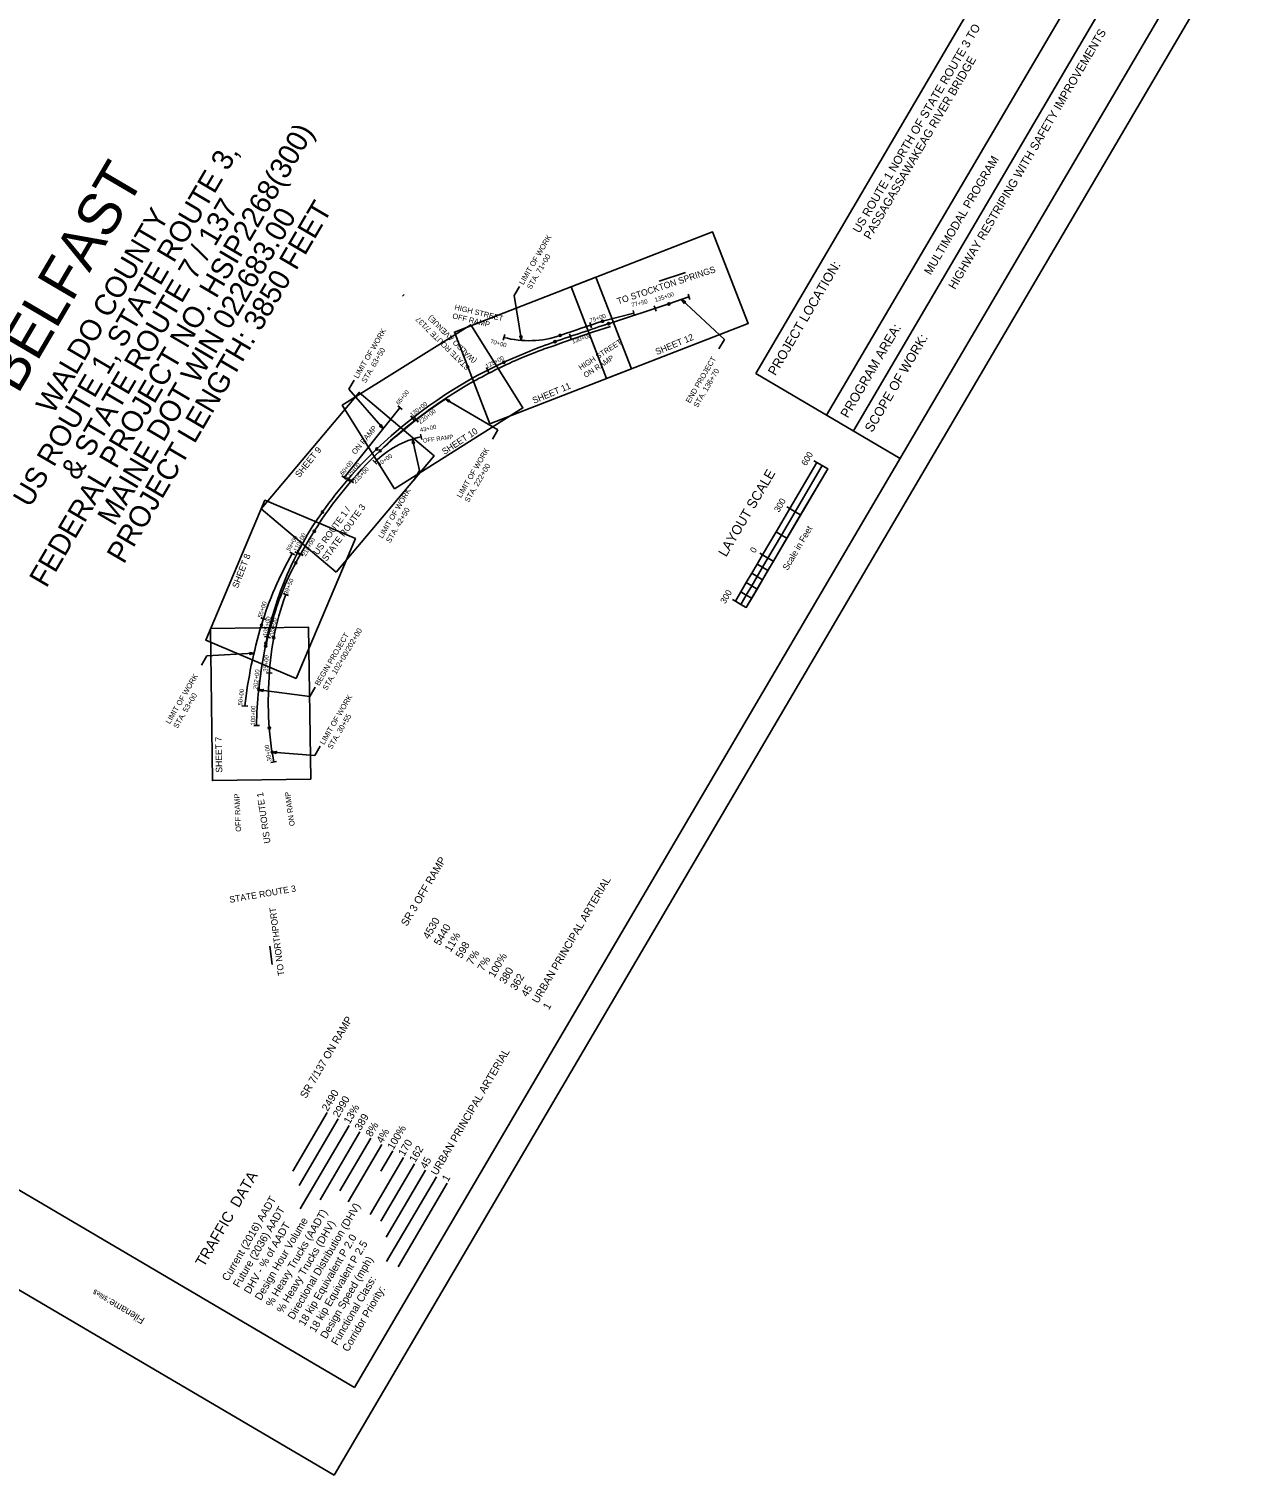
# Model space of a CAD drawing. Extents: x 423683 to 425040, y 89137 to 90655.
# Drawn here: x 424180 to 425040, y 89137 to 90149 of the extents above; entities that cross this region are included whole.
import ezdxf

# ---------------------------------------------------------------- set-up
doc = ezdxf.new("R2010")
doc.units = 0
for name, color, linetype in [('ANNOTATION', 7, 'Continuous'), ('BORDER', 7, 'Continuous'), ('D_Roadway_Centerline_Text', 7, 'Continuous'), ('D_Roadway_Edge_TW', 7, 'Continuous'), ('PLOT BOUNDARY', 7, 'Continuous'), ('Rte 1 Construction Alignment', 7, 'Continuous'), ('S_Curb_Type_5', 7, 'Continuous'), ('SHADING', 7, 'Continuous')]:
    doc.layers.add(name, color=color, linetype=linetype)

msp = doc.modelspace()

# ---------------------------------------------------------------- linework, layer by layer
at = {"layer": 'ANNOTATION'}
for p, q in [((424523.6, 89968.7), (424519.8, 89962.3)), ((424621.2, 89972.3), (424639.6, 89978.4)), ((424525, 89930.9), (424519.8, 89962.3)), ((424637, 89959.4), (424666.9, 89931.6)), ((424663.1, 89925.1), (424666.9, 89931.6)), ((424408, 89903.2), (424404.2, 89896.7)), ((424428.2, 89869.2), (424404.2, 89896.7)), ((424471.8, 89889.9), (424508.5, 89868.3)), ((424504.7, 89861.8), (424508.5, 89868.3)), ((424448.7, 89861.8), (424453.6, 89840)), ((424449.8, 89833.5), (424453.6, 89840)), ((424301, 89703.8), (424304.8, 89710.2)), ((424337.8, 89712.1), (424304.8, 89710.2)), ((424341.2, 89686.5), (424376.9, 89681.8)), ((424380.7, 89688.3), (424376.9, 89681.8)), ((424384.2, 89647.2), (424380.4, 89640.7)), ((424350.5, 89642.9), (424380.4, 89640.7)), ((424349, 89507.2), (424350.6, 89494.3)), ((424364.9, 89349.8), (424389, 89390.9)), ((424369.4, 89339.9), (424396.7, 89386.4)), ((424370.1, 89323.6), (424404.3, 89381.9)), ((424384.1, 89329.9), (424411.9, 89377.4)), ((424397.9, 89336), (424419.6, 89372.9)), ((424403.7, 89328.4), (424427.2, 89368.5)), ((424426.6, 89349.9), (424434.9, 89364)), ((424419, 89319.5), (424442.5, 89359.5)), ((424426.6, 89315), (424450.1, 89355)), ((424430.3, 89303.8), (424457.8, 89350.5)), ((424430.5, 89286.6), (424465.4, 89346)), ((424438.7, 89283), (424473, 89341.5))]:
    msp.add_line(p, q, dxfattribs=at)
for points in [[(424584.5, 89904.3), (424683.6, 89942.7), (424658.7, 90006.8), (424559.6, 89968.4)], [(424502.8, 89872.6), (424601.9, 89911), (424577, 89975.1), (424478, 89936.7)], [(424638.7, 89956.8), (424637, 89959.4), (424639.7, 89957.9)], [(424436, 89827.2), (424526, 89883.7), (424489.5, 89941.9), (424399.5, 89885.5)], [(424525.2, 89934), (424525, 89930.9), (424523.7, 89933.8)], [(424395.4, 89768.9), (424463.9, 89850.1), (424411.3, 89894.5), (424342.8, 89813.2)], [(424474, 89887.7), (424471.8, 89889.9), (424474.7, 89889)], [(424426.8, 89872), (424428.2, 89869.2), (424425.7, 89871)], [(424448.6, 89858.7), (424448.7, 89861.8), (424450.1, 89859.1)], [(424367.4, 89694.4), (424408.8, 89792.3), (424345.5, 89819.1), (424304.1, 89721.2)], [(424377.5, 89624.1), (424376, 89730.3), (424307.3, 89729.4), (424308.7, 89623.1)], [(424334.8, 89712.7), (424337.8, 89712.1), (424334.9, 89711.2)], [(424344.1, 89685.4), (424341.2, 89686.5), (424344.3, 89686.8)], [(424353.4, 89641.9), (424350.5, 89642.9), (424353.6, 89643.4)]]:
    msp.add_lwpolyline(points, close=True, dxfattribs=at)
at = {"layer": 'BORDER'}
for p, q in [((424408.2, 89198.5), (425015.8, 90233.3)), ((424876.8, 90228), (424688.8, 89907.7)), ((424738.4, 89878.6), (424926.5, 90198.8)), ((424757.2, 89867.6), (424945.2, 90187.8)), ((424688.8, 89907.7), (424789.8, 89848.4)), ((424731.6, 89845.6), (424729.6, 89846.7)), ((424712.6, 89813.3), (424710.6, 89814.4)), ((424691.7, 89782.1), (424693.6, 89780.9)), ((424674.6, 89748.6), (424672.7, 89749.7)), ((423729.1, 89597.3), (424408.2, 89198.5))]:
    msp.add_line(p, q, dxfattribs=at)
for points in [[(424682.2, 89744.1), (424739.2, 89841.1), (424731.6, 89845.6)], [(424712.6, 89813.3), (424731.6, 89845.6), (424735.4, 89843.3), (424716.4, 89811), (424712.6, 89813.3)], [(424716.4, 89811), (424735.4, 89843.3), (424739.2, 89841.1), (424720.2, 89808.8), (424716.4, 89811)], [(424716.4, 89811), (424706.9, 89794.8), (424703.1, 89797.1), (424712.6, 89813.3), (424716.4, 89811)], [(424720.2, 89808.8), (424710.7, 89792.6), (424706.9, 89794.8), (424716.4, 89811), (424720.2, 89808.8)], [(424706.9, 89794.8), (424697.4, 89778.7), (424693.6, 89780.9), (424703.1, 89797.1), (424706.9, 89794.8)], [(424710.7, 89792.6), (424701.2, 89776.4), (424697.4, 89778.7), (424706.9, 89794.8), (424710.7, 89792.6)], [(424689.8, 89774.4), (424693.6, 89780.9), (424697.4, 89778.7), (424693.6, 89772.2), (424689.8, 89774.4)], [(424693.6, 89772.2), (424697.4, 89778.7), (424701.2, 89776.4), (424697.4, 89770), (424693.6, 89772.2)], [(424682.2, 89761.5), (424686, 89768), (424689.8, 89765.7), (424686, 89759.3), (424682.2, 89761.5)], [(424686, 89768), (424689.8, 89774.4), (424693.6, 89772.2), (424689.8, 89765.7), (424686, 89768)], [(424689.8, 89765.7), (424693.6, 89772.2), (424697.4, 89770), (424693.6, 89763.5), (424689.8, 89765.7)], [(424678.4, 89755), (424682.2, 89761.5), (424686, 89759.3), (424682.2, 89752.8), (424678.4, 89755)], [(424682.2, 89752.8), (424686, 89759.3), (424689.8, 89757), (424686, 89750.6), (424682.2, 89752.8)], [(424686, 89759.3), (424689.8, 89765.7), (424693.6, 89763.5), (424689.8, 89757), (424686, 89759.3)], [(424674.6, 89748.6), (424678.4, 89755), (424682.2, 89752.8), (424678.4, 89746.3), (424674.6, 89748.6)], [(424678.4, 89746.3), (424682.2, 89752.8), (424686, 89750.6), (424682.2, 89744.1), (424678.4, 89746.3)]]:
    msp.add_lwpolyline(points, dxfattribs=at)
for points in [[(424716.4, 89811), (424735.4, 89843.3), (424739.2, 89841.1), (424720.2, 89808.8)], [(424706.9, 89794.8), (424716.4, 89811), (424712.6, 89813.3), (424703.1, 89797.1)], [(424697.4, 89778.7), (424706.9, 89794.8), (424710.7, 89792.6), (424701.2, 89776.4)], [(424693.6, 89772.2), (424697.4, 89778.7), (424693.6, 89780.9), (424689.8, 89774.4)], [(424686, 89759.3), (424689.8, 89765.7), (424686, 89768), (424682.2, 89761.5)], [(424689.8, 89765.7), (424693.6, 89772.2), (424697.4, 89770), (424693.6, 89763.5)], [(424682.2, 89752.8), (424686, 89759.3), (424689.8, 89757), (424686, 89750.6)], [(424674.6, 89748.6), (424678.4, 89755), (424682.2, 89752.8), (424678.4, 89746.3)]]:
    msp.add_lwpolyline(points, close=True, dxfattribs=at)
at = {"layer": 'D_Roadway_Centerline_Text'}
for points in [[(424641.5, 89963.2), (424642.8, 89959.4)], [(424603, 89951.9), (424604, 89948)], [(424603.4, 89950.2), (424603.5, 89949.7)], [(424617.8, 89955.2), (424619.1, 89951.4)], [(424572.7, 89943.5), (424574, 89939.7)], [(424513.2, 89935), (424512.1, 89931.1)], [(424558.5, 89935.5), (424559.8, 89931.7)], [(424500.4, 89911.9), (424502.2, 89908.3)], [(424471.6, 89890.1), (424471.9, 89889.6)], [(424438.4, 89885.1), (424441.5, 89882.6)], [(424447.5, 89878.1), (424449.9, 89875)], [(424450.2, 89876.9), (424452.6, 89873.8)], [(424454.3, 89865.4), (424455.2, 89861.5)], [(424420.9, 89847.1), (424423.7, 89844.3)], [(424399.3, 89836.3), (424402.4, 89833.8)], [(424401.9, 89834.8), (424405, 89832.2)], [(424404.5, 89833.9), (424407.5, 89831.3)], [(424362.9, 89782.9), (424366.4, 89780.9)], [(424366.4, 89783.1), (424369.9, 89781.2)], [(424368.6, 89782.3), (424372.1, 89780.4)], [(424358.3, 89753.9), (424362, 89752.4)], [(424342.6, 89736.8), (424346.4, 89735.6)], [(424345.1, 89723.9), (424349, 89723.1)], [(424345.6, 89723.9), (424349.4, 89722.9)], [(424346.6, 89698.5), (424350.6, 89698.2)], [(424329.4, 89675.4), (424333.4, 89675)], [(424337.6, 89661.6), (424341.6, 89661.5)], [(424349.7, 89635.8), (424353.6, 89636.5)]]:
    msp.add_lwpolyline(points, dxfattribs=at)
at = {"layer": 'D_Roadway_Edge_TW'}
for p, q in [((424628.1, 89956.4), (424642.1, 89961.3)), ((424581.6, 89944.3), (424603.5, 89949.9)), ((424585.9, 89942.6), (424628.1, 89956.4)), ((424400.8, 89835.1), (424439.9, 89883.8)), ((424351.7, 89636.1), (424350.5, 89642.9))]:
    msp.add_line(p, q, dxfattribs=at)
for centre, radius, start, end in [((425487.9, 87197.2), 2889.8, 108.1874, 108.9737), ((425487.9, 87197.2), 2892.8, 108.2581, 108.877), ((424530.2, 89998.2), 67.5, 254.9678, 288.877), ((424670.8, 89573.8), 376.6, 108.9737, 114.8373), ((424649.8, 89619.2), 326.6, 114.8373, 133.776), ((424651, 89617), 326.5, 123.3035, 133.5362), ((424468.4, 89799.9), 65, 102.0988, 135.1541), ((424629.9, 89639.2), 295.9, 133.5362, 147.6604), ((424639, 89630.5), 311, 133.776, 144.5408), ((424579.1, 89673.1), 237.5, 144.5408, 168.8381), ((424671.7, 89612.8), 345.3, 147.6604, 151.9147), ((424574.6, 89661.9), 241.9, 150.2569, 163.2266), ((424548.7, 89678.4), 205.9, 151.9112, 164.4564), ((424501.1, 89697.3), 151.6, 158.3641, 170.2343), ((424654.2, 89637.9), 325, 163.2266, 173.4073), ((424547.3, 89672.9), 206.1, 162.8833, 167.5733), ((424708.9, 89647.5), 369.8, 168.8381, 173.9451), ((424644.7, 89654.3), 305.3, 168.0988, 173.9451), ((424610.3, 89678.5), 262.5, 170.2343, 184.0825), ((424644.7, 89654.3), 305.3, 173.9451, 178.6375), ((424524.9, 89672.4), 176.9, 184.0825, 189.5944)]:
    msp.add_arc(centre, radius, start, end, dxfattribs=at)
at = {"layer": 'PLOT BOUNDARY'}
msp.add_lwpolyline([(424394, 89137.3), (425039.6, 90236.7), (424328.2, 90654.5), (423682.6, 89555.1)], close=True, dxfattribs=at)
at = {"layer": 'Rte 1 Construction Alignment'}
for centre in [(424628.1, 89956.4), (424581.6, 89944.3), (424585.9, 89942.6), (424548.4, 89930), (424552, 89934.4), (424512.6, 89915.6), (424423.8, 89855), (424426.1, 89853.7), (424385.7, 89810.9), (424380, 89797.4), (424367.1, 89775.3), (424343.1, 89731.7), (424346, 89717.2), (424346.1, 89719.1), (424351.6, 89723), (424341.2, 89686.5), (424348.5, 89659.8), (424350.5, 89642.9)]:
    msp.add_circle(centre, 0.75, dxfattribs=at)
at = {"layer": 'S_Curb_Type_5'}
msp.add_lwpolyline([(424587.2, 89940.7), (424575.3, 89936.8), (424568.5, 89934.5), (424561.8, 89932.2), (424554.3, 89929.6), (424547.6, 89927.2), (424546.1, 89926.7), (424543.1, 89925.7), (424540.9, 89924.9), (424539.5, 89924.4), (424536.7, 89923.3), (424534.6, 89922.5), (424532.6, 89921.7), (424528.5, 89920.1), (424524.5, 89918.4), (424522.5, 89917.6), (424520.4, 89916.7), (424519, 89916.1), (424516.3, 89914.8), (424514, 89913.8), (424509.4, 89911.6), (424507, 89910.5), (424505.9, 89909.9), (424504.2, 89909), (424500.7, 89907.2), (424499.5, 89906.6), (424497.1, 89905.3), (424495.3, 89904.4), (424493.4, 89903.3), (424492.1, 89902.6), (424489.6, 89901.2), (424487.9, 89900.2), (424484.3, 89898.1), (424480.6, 89895.8), (424478.7, 89894.7), (424475.8, 89892.8), (424474.3, 89891.9), (424472.4, 89890.7), (424471.2, 89889.9), (424468.7, 89888.2), (424467, 89887), (424463.6, 89884.7), (424461.3, 89883.1), (424460.2, 89882.3), (424458.5, 89881), (424453.1, 89877), (424449.3, 89874.1), (424444, 89869.9), (424438.5, 89865.2), (424433.4, 89860.8), (424429.5, 89857.2)], dxfattribs=at)
at = {"layer": 'SHADING'}
msp.add_line((424442.9, 89963), (424441.6, 89961.8), dxfattribs=at)

# ---------------------------------------------------------------- texts
at = {"layer": 'ANNOTATION'}
for s, height, rotation, p in [('US ROUTE 1 NORTH OF STATE ROUTE 3 TO', 5.893, 59.5766, (424761.4, 90005.5)), ('HIGHWAY RESTRIPING WITH SAFETY IMPROVEMENTS', 5.893, 59.5766, (424828.3, 89966.1)), ('PASSAGASSAWAKEAG RIVER BRIDGE', 5.893, 59.5766, (424769, 90001)), ('MULTIMODAL PROGRAM', 5.893, 59.5766, (424811.3, 89976.2)), ('LIMIT OF WORK', 3.75, 59.5766, (424526.2, 89969.4)), ('STA. 71+00', 3.75, 59.5766, (424531.6, 89966.2)), ('TO STOCKTON SPRINGS', 4.5, 18.3204, (424592.6, 89956)), ('PROJECT LOCATION:', 6.562, 59.5766, (424702.6, 89905.8)), ('OFF RAMP', 3.75, 346.4532, (424476.3, 89946.4)), ('HIGH STREET', 3.75, 346.4532, (424477.8, 89952.5)), ('LIMIT OF WORK', 3.75, 59.5766, (424410.5, 89903.9)), ('STATE ROUTE 7/137', 3.75, 135.3069, (424489.1, 89912.3)), ('(WALDO AVENUE)', 3.75, 135.3069, (424493.8, 89917.1)), ('PROGRAM AREA:', 6.562, 59.5766, (424753.3, 89876.1)), ('HIGH STREET', 3.75, 33.0239, (424566.4, 89909.9)), ('SHEET 12', 4.5, 22.7291, (424619.7, 89920.6)), ('SCOPE OF WORK:', 6.562, 59.5766, (424770.3, 89866.1)), ('STA. 63+50', 3.75, 59.5766, (424415.9, 89900.7)), ('ON RAMP', 3.75, 33.0239, (424569.8, 89904.6)), ('END PROJECT', 3.75, 59.5766, (424642.8, 89886.7)), ('STA. 136+70', 3.75, 59.5766, (424648.2, 89883.6)), ('SHEET 11', 4.5, 22.7291, (424533.7, 89886.5)), ('ON RAMP', 3.75, 50.4005, (424408.7, 89850.8)), ('SHEET 10', 4.5, 33.3606, (424471.1, 89850.7)), ('OFF RAMP', 3, 7.5861, (424456.2, 89859.3)), ('SHEET 9', 4.5, 51.0857, (424369.6, 89834.6)), ('LIMIT OF WORK', 3.75, 59.5766, (424482.6, 89820.4)), ('STA. 222+00', 3.75, 59.5766, (424488, 89817.2)), ('LIMIT OF WORK', 3.75, 59.5766, (424427.7, 89792.1)), ('US ROUTE 1 / ', 4.5, 54.22, (424382.5, 89780.4)), ('STATE ROUTE 3', 4.5, 54.22, (424388.6, 89776.1)), ('STA. 42+50', 3.75, 59.5766, (424433.1, 89788.9)), ('SHEET 8', 4.5, 68.742, (424326.5, 89757.2)), ('STA. 102+00/202+00', 3.75, 59.5766, (424388.7, 89685.8)), ('BEGIN PROJECT', 3.75, 59.5766, (424383.3, 89689)), ('LIMIT OF WORK', 3.75, 59.5766, (424278.9, 89662.3)), ('STA. 53+00', 3.75, 59.5766, (424284.3, 89659.2)), ('LIMIT OF WORK', 3.75, 59.5766, (424386.8, 89647.8)), ('STA. 30+55', 3.75, 59.5766, (424392.2, 89644.6)), ('SHEET 7', 4.5, 90.7839, (424315.6, 89628.6)), ('US ROUTE 1', 4.5, 98.4487, (424349.4, 89579.4)), ('OFF RAMP', 3.75, 92.532, (424328.8, 89587.3)), ('ON RAMP', 3.75, 98.0754, (424366.4, 89591.5)), ('SR 3 OFF RAMP', 5.315, 59.5766, (424444.8, 89520.7)), ('URBAN PRINCIPAL ARTERIAL', 5.315, 59.5766, (424536.5, 89466.8)), ('STATE ROUTE 3', 4.5, 9.7182, (424321, 89537.5)), ('TO NORTHPORT', 4.5, 97.2548, (424359.1, 89486.8)), ('4530', 5.31, 59.5766, (424460.1, 89511.7)), ('5440', 5.31, 59.5766, (424467.8, 89507.2)), ('11%', 5.31, 59.5766, (424475.4, 89502.7)), ('598', 5.31, 59.5766, (424483, 89498.2)), ('7%', 5.31, 59.5766, (424490.7, 89493.7)), ('7%', 5.31, 59.5766, (424498.3, 89489.3)), ('100%', 5.31, 59.5766, (424505.9, 89484.8)), ('380', 5.31, 59.5766, (424513.6, 89480.3)), ('362', 5.31, 59.5766, (424521.2, 89475.8)), ('45', 5.31, 59.5766, (424528.9, 89471.3)), ('1', 5.31, 59.5766, (424544.1, 89462.3)), ('SR 7/137 ON RAMP', 5.315, 59.5766, (424374.2, 89400.3)), ('URBAN PRINCIPAL ARTERIAL', 5.315, 59.5766, (424465.8, 89346.5)), ('2490', 5.31, 59.5766, (424389.4, 89391.3)), ('2990', 5.31, 59.5766, (424397.1, 89386.9)), ('13%', 5.31, 59.5766, (424404.7, 89382.4)), ('389', 5.31, 59.5766, (424412.4, 89377.9)), ('8%', 5.31, 59.5766, (424420, 89373.4)), ('4%', 5.31, 59.5766, (424427.6, 89368.9)), ('100%', 5.31, 59.5766, (424435.3, 89364.4)), ('170', 5.31, 59.5766, (424442.9, 89359.9)), ('162', 5.31, 59.5766, (424450.6, 89355.5)), ('45', 5.31, 59.5766, (424458.2, 89351)), ('TRAFFIC  DATA', 7.53, 59.5766, (424302.8, 89282.3)), ('1', 5.31, 59.5766, (424473.5, 89342)), ('Current (2016) AADT', 5.315, 59.5766, (424319.6, 89272.5)), ('Future (2036) AADT', 5.315, 59.5766, (424327.3, 89268)), ('% Heavy Trucks (AADT)', 5.315, 59.5766, (424350.2, 89254.5)), ('Directional Distribution (DHV)', 5.315, 59.5766, (424365.5, 89245.6)), ('DHV - % of AADT', 5.315, 59.5766, (424334.9, 89263.5)), ('Design Hour Volume', 5.315, 59.5766, (424342.6, 89259)), ('% Heavy Trucks (DHV)', 5.315, 59.5766, (424357.8, 89250.1)), ('18 kip Equivalent P 2.0', 5.315, 59.5766, (424373.1, 89241.1)), ('18 kip Equivalent P 2.5', 5.315, 59.5766, (424380.7, 89236.6)), ('Design Speed (mph)', 5.315, 59.5766, (424388.4, 89232.1)), ('Functional Class:', 5.315, 59.5766, (424396, 89227.6)), ('Corridor Priority:', 5.315, 59.5766, (424403.7, 89223.1))]:
    msp.add_text(s, height=height, rotation=rotation, dxfattribs=at).set_placement(p)
at = {"layer": 'BORDER'}
for s, height, rotation, p in [('DEPARTMENT  OF  TRANSPORTATION', 18.749, 59.5766, (423967.7, 89831.5)), ('FEDERAL PROJECT NO. HSIP2268(300)', 14.763, 59.5766, (424192.5, 89757.2)), ('US ROUTE 1, STATE ROUTE 3,', 14.763, 59.5766, (424181.1, 89813.3)), ('BELFAST', 29.53, 59.5766, (424172.6, 89892.7)), ('& STATE ROUTE 7 / 137', 14.763, 59.5766, (424214.4, 89832.3)), ('PROJECT LENGTH: 3850 FEET', 14.763, 59.5766, (424246.7, 89773.9)), ('WALDO COUNTY', 14.763, 59.5766, (424197.2, 89878.6)), ('MAINE DOT WIN 022683.00', 14.763, 59.5766, (424240.1, 89800.4)), ('600', 4.43, 59.5766, (424724.2, 89842.8)), ('LAYOUT SCALE', 6.791, 59.5766, (424668.1, 89779)), ('300', 4.43, 59.5766, (424705.1, 89810.3)), ('Scale in Feet', 4.429, 59.5766, (424711.2, 89769.7)), ('0', 4.43, 59.5766, (424688.3, 89781.8)), ('300', 4.43, 59.5766, (424667.5, 89746.3)), ('$file$', 3.35, 149.5766, (424236, 89261.8)), ('Filename:', 5.02, 149.5766, (424261.8, 89246.9))]:
    msp.add_text(s, height=height, rotation=rotation, dxfattribs=at).set_placement(p)
at = {"layer": 'D_Roadway_Centerline_Text'}
for s, height, rotation, p in [('77+50', 3, 14.3792, (424602.2, 89954.1)), ('135+00', 3, 18.1874, (424618.7, 89957.7)), ('75+00', 3, 18.4304, (424573.2, 89943.2)), ('70+00', 3, 344.9678, (424502.8, 89929)), ('130+00', 3, 18.7479, (424560.8, 89928.6)), ('125+00', 3, 27.0419, (424500.7, 89911.3)), ('65+00', 3, 51.2548, (424439.2, 89885.6)), ('222+00', 0.375, 33.3035, (424471.8, 89890.1)), ('120+00', 3, 38.0055, (424448.4, 89877.3)), ('220+00', 3, 37.6869, (424454.3, 89872.3)), ('43+00', 3, 12.0988, (424454.2, 89866.7)), ('40+00', 3, 35.2101, (424425.4, 89842.7)), ('60+00', 3, 51.2548, (424400, 89836.3)), ('115+00', 3, 49.23, (424403.3, 89833.3)), ('215+00', 3, 46.3373, (424408.8, 89830.5)), ('59+00', 3, 60.2569, (424362.8, 89783.2)), ('110+00', 3, 62.6643, (424367.8, 89782.8)), ('210+00', 3, 60.7688, (424373.9, 89779.6)), ('39+50', 3, 68.3641, (424361.3, 89752.8)), ('55+00', 3, 72.101, (424343.2, 89736.7)), ('105+00', 3, 77.7421, (424346.7, 89723.8)), ('205+00', 3, 75.8073, (424350.6, 89722.8)), ('35+00', 3, 85.6555, (424347.3, 89699)), ('202+00', 3, 83.9451, (424340.2, 89686.8)), ('50+00', 3, 83.4073, (424329.5, 89675.4)), ('100+00', 3, 88.6375, (424338.5, 89661.5)), ('30+00', 3, 99.5944, (424350.1, 89636.8))]:
    msp.add_text(s, height=height, rotation=rotation, dxfattribs=at).set_placement(p)

doc.saveas('drawing.dxf')
